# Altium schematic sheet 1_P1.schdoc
size 429 x 307 mm; Symbol: Drawing-Symbol_A4; Device: Drawing-Symbol_A4; Company: 嘉立创EDA; Version: V1.0; Page Size: A4; @Project Name: PCBFinal; @Page Count: 1; @Update Date: 2025-08-18; @Create Date: 2025-08-09; @Schematic Name: Schematic1; @Page No: 1; @Page Name: P1; @Create Time: 00:14:34; @Update Time: 05:11:40; Width: 1655; Height: 1170; Region Start: 1; X Region Count: 6; Y Region Count: 4; Blade Width: 10; Title Block Position: 3; @Board Name: Board1
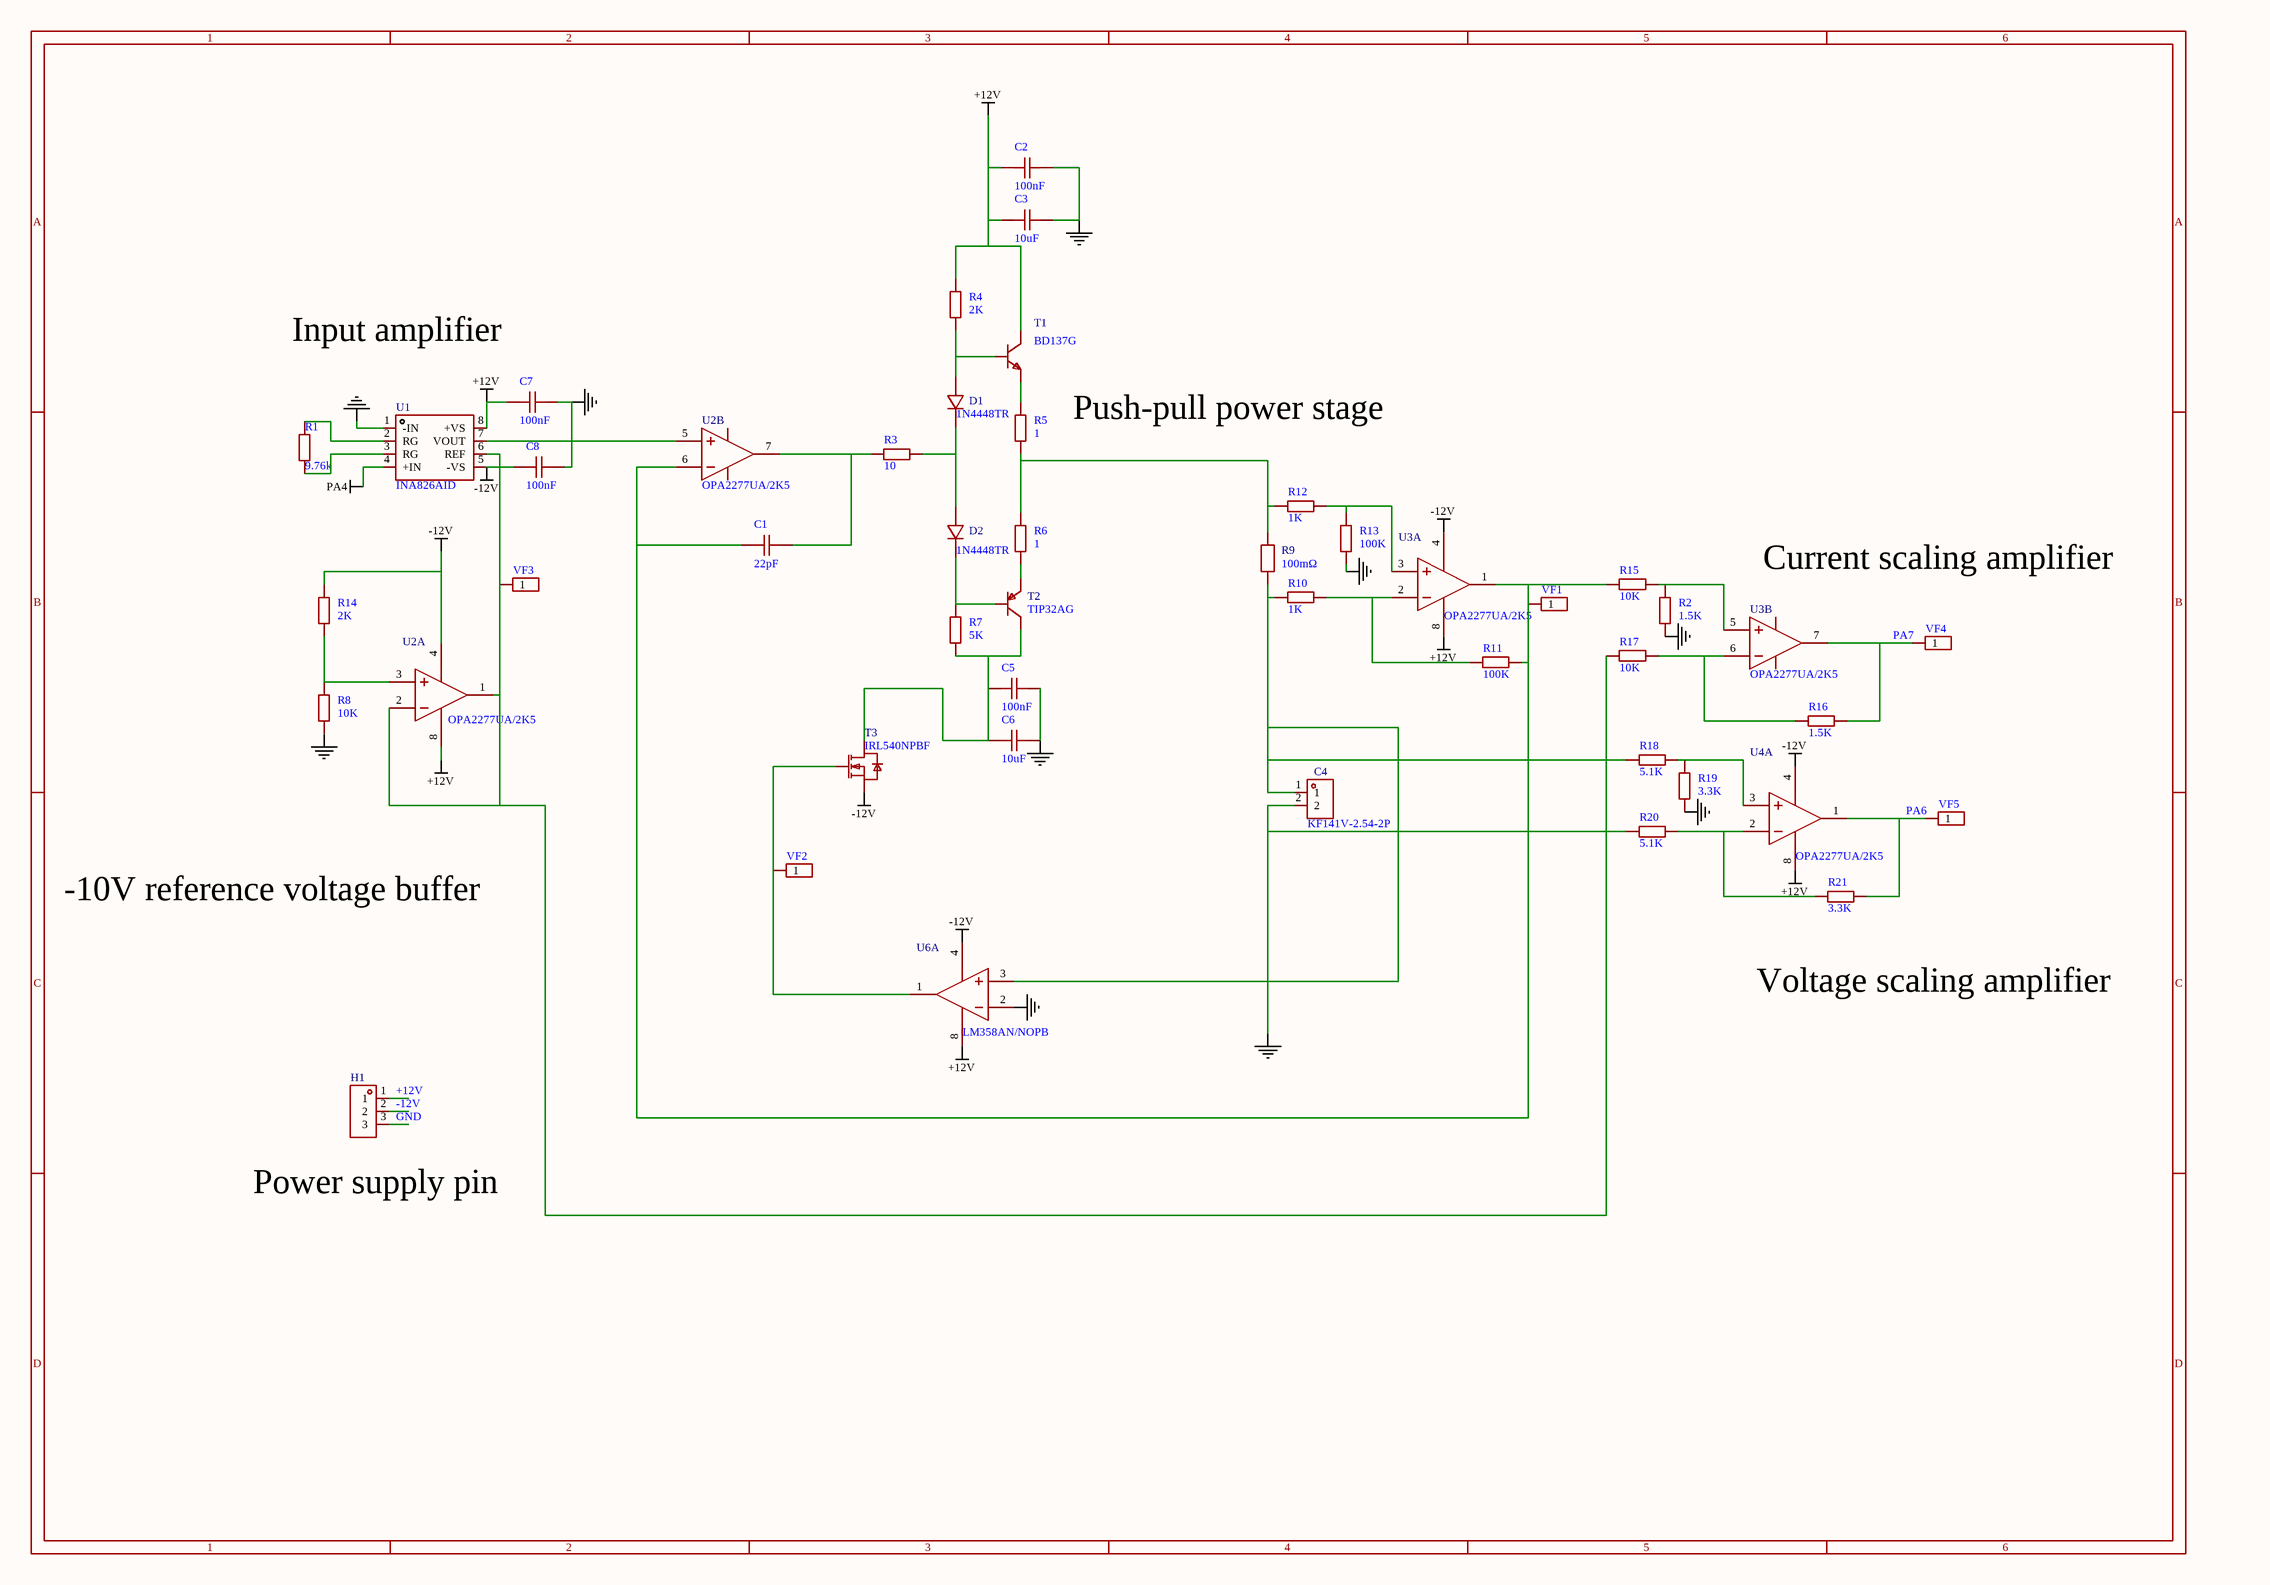
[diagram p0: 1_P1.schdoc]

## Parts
C1  22pF  [C0805]
C2  100nF  [C0805]
C3  10uF  [C0805]
C4  KF141V-2.54-2P  [CONN-TH_2P-P2.54_KF141V-2.54-2P]
C5  100nF  [C0805]
C6  10uF  [C0805]
C7  100nF  [C0805]
C8  100nF  [C0805]
D1  1N4448TR  [DO-35_BD2.0-L4.2-P8.20-D0.5-RD]
D2  1N4448TR  [DO-35_BD2.0-L4.2-P8.20-D0.5-RD]
H1  (no value)  [HDR-TH_3P-P2.54-V-F]
R1  9.76k  [R0805]
R2  1.5K  [R0805]
R3  10  [R0805]
R4  2K  [R0805]
R5  1  [R0805]
R6  1  [R0805]
R7  5K  [R0805]
R8  10K  [R0805]
R9  100mΩ  [RES-TH_BD8.4-L23.8-P27.8-D1.0]
R10  1K  [R0805]
R11  100K  [R0805]
R12  1K  [R0805]
R13  100K  [R0805]
R14  2K  [R0805]
R15  10K  [R0805]
R16  1.5K  [R0805]
R17  10K  [R0805]
R18  5.1K  [R0805]
R19  3.3K  [R0805]
R20  5.1K  [R0805]
R21  3.3K  [R0805]
T1  BD137G  [TO-225-3_L7.6-W2.8-P2.54-L]
T2  TIP32AG  [TO-220-3_L10.0-W4.5-P2.54-L]
T3  IRL540NPBF  [TO-220AB-3_L10.4-W4.6-P2.54-L]
U1  INA826AID  [SOIC-8_L4.9-W3.9-P1.27-LS6.0-BL]
U2  OPA2277UA/2K5  [SOIC-8_L5.0-W4.0-P1.27-LS6.0-BL]  (parts A,B of 2)
U3  OPA2277UA/2K5  [SOIC-8_L5.0-W4.0-P1.27-LS6.0-BL]  (parts A,B of 2)
U4  OPA2277UA/2K5  [SOIC-8_L5.0-W4.0-P1.27-LS6.0-BL]  (part A of 2)
U6  LM358AN/NOPB  [PDIP-8_L10.2-W6.5-P2.54-LS7.6-BL]  (part A of 2)
VF1  (no value)  [HDR-TH_1P-V-M_XKB_X4611WV-01I-C28D40]
VF2  (no value)  [HDR-TH_1P-V-M_XKB_X4611WV-01I-C28D40]
VF3  (no value)  [HDR-TH_1P-V-M_XKB_X4611WV-01I-C28D40]
VF4  (no value)  [HDR-TH_1P-V-M_XKB_X4611WV-01I-C28D40]
VF5  (no value)  [HDR-TH_1P-V-M_XKB_X4611WV-01I-C28D40]

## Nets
+12V: C2.1 C3.1 C7.2 H1.1 R4.2 T1.2 U1.8(+VS) U2.8(V+) U3.8(V+) U4.8(V+) U6.8(V+)
-12V: C8.2 H1.2 R14.2 T3.3(S) U1.5(-VS) U2.4(V-) U3.4(V-) U4.4(V-) U6.4(GND)
GND: C2.2 C3.2 C4.2 C5.2 C6.2 C7.1 C8.1 H1.3 R2.1 R8.1 R13.1 R19.1 R20.2 U1.1(-IN) U6.2(INA-)
PA4: U1.4(+IN)
PA6: R21.2 U4.1(OUT_A) VF5.1
PA7: R16.2 U3.7(OUT_B) VF4.1
NetC1_1: C1.1 R11.2 R15.1 U2.6(IN_B-) U3.1(OUT_A) VF1.1
NetC1_2: C1.2 R3.2 U2.7(OUT_B)
NetC4_1: C4.1 R9.1 R10.2 R18.1 U6.3(INA+)
NetC5_1: C5.1 C6.1 R7.1 T2.2(C) T3.2(D)
NetD1_1: D1.1 D2.2 R3.1
NetD1_2: D1.2 R4.1 T1.3
NetD2_1: D2.1 R7.2 T2.1(B)
NetR1_1: R1.1 U1.3(RG)
NetR1_2: R1.2 U1.2(RG)
NetR2_2: R2.2 R15.2 U3.5(IN_B+)
NetR5_1: R5.1 R6.2 R9.2 R12.1
NetR5_2: R5.2 T1.1
NetR6_1: R6.1 T2.3(E)
NetR8_2: R8.2 R14.1 U2.3(IN_A+)
NetR10_1: R10.1 R11.1 U3.2(IN_A-)
NetR12_2: R12.2 R13.2 U3.3(IN_A+)
NetR16_1: R16.1 R17.1 U3.6(IN_B-)
NetR17_2: R17.2 U1.6(REF) U2.1(OUT_A) U2.2(IN_A-) VF3.1
NetR18_2: R18.2 R19.2 U4.3(IN_A+)
NetR20_1: R20.1 R21.1 U4.2(IN_A-)
NetT3_1: T3.1(G) U6.1(OUTA) VF2.1
NetU1_7: U1.7(VOUT) U2.5(IN_B+)

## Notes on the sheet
- Input amplifier
- Push-pull power stage
- Current scaling amplifier
- -10V reference voltage buffer
- Voltage scaling amplifier
- (near H1) Power supply pin

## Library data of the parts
C1-C3 C5-C8 = CAP_0805: Symbol: CapAcitance; Convert to PCB: yes
C4 = KF141V-2.54-2P: Manufacturer: KEFA(科发); Add into BOM: yes; Pitch: 2.54mm; Number of PINs Per Row: 2; Current Rating (Max): 2A; Voltage Rating (Max): 150V; Wire Gauge - AWG: 20~26; Wire Gauge - mm2: 1
D1 D2 = 1N4448TR: Manufacturer: onsemi(安森美); Add into BOM: yes; Forward Voltage (Vf@If): 1V@100mA; Reverse Voltage (Vr): 100V; Rectified Current: 200mA; Reverse Leakage Current: 5uA@75V; Reverse Recovery Time (trr): 4ns
H1 = HDR-F_2.54_1x3P: Symbol: PM254V-11-03-H85; Convert to PCB: yes
R1-R8 R10-R21 = Res_0805: Symbol: 电阻; Convert to PCB: yes
R9 = 15FR100E-T: Manufacturer: Ohmite; Add into BOM: yes; Tolerance: ±1%; Power(Watts): 5W; Temperature Coefficient: ±50ppm/℃
T1 = MJE182G: Manufacturer: onsemi(安森美); Symbol: MJE182; Add into BOM: yes; type: NPN; Current - Collector(Ic): 3A; Collector - Emitter Voltage VCEO: 100V; Pd - Power Dissipation: 12.5W; DC Current Gain: 50@100mA,1.0V; Transition frequency(fT): 50MHz; Current - Collector Cutoff: 100uA; Vce Saturation(VCE(sat)): 1.7V
T2 = TIP32AG: Manufacturer: onsemi(安森美); Add into BOM: yes; Transistor Type: PNP; Collector Current (Ic): 3A; Collector-Emitter Breakdown Voltage (Vceo): 60V; Power Dissipation (Pd): 40W; DC Current Gain (hFE@Ic,Vce): 25@1.0A,4.0V; Transition Frequency (fT): 3MHz; Collector Cut-Off Current (Icbo): 300uA; Collector-Emitter Saturation Voltage (VCE(sat)@Ic,Ib): 1.2V@3.0A,375mA
T3 = IRL540NPBF-VB: Manufacturer: VBsemi(微碧半导体); Add into BOM: yes; Type: 1个N沟道; Drain to Source Voltage: 100V; Current - Continuous Drain(Id): 55A; RDS(on): 36mΩ@10V,5A; Pd - Power Dissipation: 127W; Gate Threshold Voltage (Vgs(th)@Id): 3V; Gate Charge(Qg): 60nC@10V; Input Capacitance(Ciss@Vds): 4.5nF@50V; Reverse Transfer Capacitance (Crss@Vds): 90pF@25V
U1 = INA826AID: Manufacturer: TI(德州仪器); Add into BOM: yes; Number of Circuits: 单路; Current - Input Bias(Ib): 35nA; Voltage - Input Offset(Vos): 40uV; Slew Rate(SR): 1V/us; -3db Bandwidth: 1MHz
U2-U4 = OPA2277UA/2K5: Manufacturer: TI(德州仪器); Add into BOM: yes; Number of Circuits: 双路; Gain Bandwidth Product(GBP): 1MHz; Current - Input Bias(Ib): 4nA; Slew Rate(SR): 0.8V/us; Output Current: 35mA; Supply Current: 790uA; Relevance: []
U6 = LM358AN/NOPB: Manufacturer: TI(德州仪器); Add into BOM: yes; Number of Circuits: 双路; Gain Bandwidth Product(GBP): 1MHz; Current - Input Bias(Ib): 45nA; Output Current: 40mA; Relevance: []
VF1-VF5 = HDR-M_2.54_1x1P: Symbol: HDR_1x1; Convert to PCB: yes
